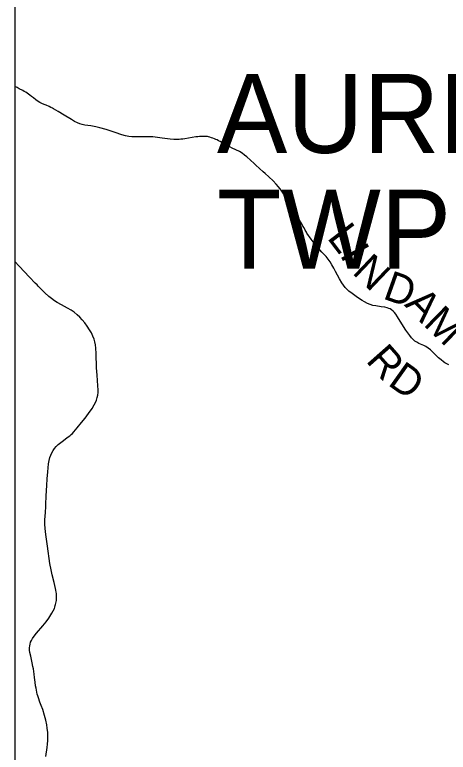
# Model space of a CAD drawing. Extents: x -10.5 to 40.6, y -3.2 to 22.
# Drawn here: x -10.544 to -9.719, y 16.355 to 17.758 of the extents above; entities that cross this region are included whole.
import ezdxf

# ---------------------------------------------------------------- set-up
doc = ezdxf.new("R2010")
doc.units = 0
for name, color, linetype in [('GM_X_Township_Road', 7, 'Continuous'), ('GM_X_Township_Road_Text', 7, 'Continuous'), ('GM_X_Township_Text', 7, 'Continuous')]:
    doc.layers.add(name, color=color, linetype=linetype)

msp = doc.modelspace()

# ---------------------------------------------------------------- linework, layer by layer
at = {"layer": 'GM_X_Township_Road'}
for points in [[(-9.7184, 17.092), (-9.7206, 17.093), (-9.7234, 17.0946), (-9.7257, 17.0959), (-9.7281, 17.0976), (-9.733, 17.1013), (-9.7376, 17.1054), (-9.7478, 17.1154), (-9.7533, 17.1205), (-9.7577, 17.124), (-9.7618, 17.1267), (-9.7657, 17.1287), (-9.7754, 17.1328), (-9.7793, 17.1348), (-9.7829, 17.1371), (-9.7863, 17.1399), (-9.7893, 17.1431), (-9.7927, 17.1475), (-9.8001, 17.1582), (-9.8076, 17.1697), (-9.816, 17.1835), (-9.8191, 17.1882), (-9.8218, 17.1916), (-9.8244, 17.1942), (-9.8273, 17.1965), (-9.8299, 17.1982), (-9.8327, 17.1994), (-9.8357, 17.2004), (-9.8399, 17.2014), (-9.8473, 17.2025), (-9.8571, 17.2039), (-9.8626, 17.2051), (-9.8679, 17.2067), (-9.8731, 17.2088), (-9.8786, 17.2116), (-9.8833, 17.2144), (-9.8923, 17.2202), (-9.9023, 17.2275), (-9.9083, 17.2322), (-9.9122, 17.2358), (-9.9154, 17.2392), (-9.9187, 17.2433), (-9.922, 17.2481), (-9.9264, 17.2556), (-9.934, 17.2695), (-9.9373, 17.2757), (-9.9407, 17.2821), (-9.9442, 17.2879), (-9.9478, 17.2929), (-9.9517, 17.2977), (-9.9555, 17.3018), (-9.9597, 17.3063), (-9.9635, 17.3104), (-9.9666, 17.314), (-9.97, 17.318), (-9.9733, 17.322), (-9.9766, 17.3261), (-9.9784, 17.3284), (-9.9805, 17.3312), (-9.9834, 17.3351), (-9.9855, 17.3381), (-9.9883, 17.3423), (-9.9893, 17.3441), (-9.9917, 17.3483), (-9.9938, 17.3523), (-9.9958, 17.3558), (-9.9981, 17.3599), (-10.0005, 17.3641), (-10.0033, 17.3688), (-10.0065, 17.3741), (-10.009, 17.3784), (-10.0116, 17.3826), (-10.0142, 17.3868), (-10.0175, 17.3921), (-10.0226, 17.4005), (-10.0325, 17.4164), (-10.0375, 17.424), (-10.0423, 17.4303), (-10.0466, 17.4354), (-10.0524, 17.4416), (-10.0608, 17.4495), (-10.0675, 17.4556), (-10.0715, 17.4591), (-10.0853, 17.4715), (-10.0889, 17.4748), (-10.1026, 17.4874), (-10.1069, 17.4909), (-10.1115, 17.4942), (-10.1168, 17.4974), (-10.1234, 17.5009), (-10.1305, 17.5042), (-10.1353, 17.5064), (-10.1391, 17.5083), (-10.1429, 17.5101), (-10.1463, 17.512), (-10.1537, 17.5165), (-10.1565, 17.5182), (-10.1591, 17.5196), (-10.1614, 17.5207), (-10.1642, 17.5219), (-10.1672, 17.523), (-10.1701, 17.5239), (-10.1729, 17.5247), (-10.1755, 17.5253), (-10.1778, 17.5259), (-10.1807, 17.5263), (-10.1835, 17.5264), (-10.1866, 17.5264), (-10.1895, 17.5264), (-10.1928, 17.5261), (-10.1961, 17.5258), (-10.1996, 17.5253), (-10.2204, 17.5219), (-10.2245, 17.5213), (-10.2285, 17.521), (-10.2318, 17.5207), (-10.2353, 17.5206), (-10.2415, 17.5206), (-10.2489, 17.5212), (-10.2637, 17.523), (-10.2816, 17.5252), (-10.289, 17.5257), (-10.2959, 17.5258), (-10.3064, 17.5255), (-10.3151, 17.5253), (-10.3213, 17.5257), (-10.3275, 17.5264), (-10.3336, 17.5277), (-10.3408, 17.5296), (-10.3532, 17.5335), (-10.3703, 17.5392), (-10.3823, 17.5426), (-10.3901, 17.5444), (-10.3999, 17.5463), (-10.4109, 17.5479), (-10.4164, 17.549), (-10.4206, 17.5502), (-10.4252, 17.552), (-10.4307, 17.5548), (-10.4366, 17.5584), (-10.4503, 17.5669), (-10.462, 17.5739), (-10.4706, 17.5789), (-10.4728, 17.58), (-10.4755, 17.5815), (-10.4789, 17.5831), (-10.4847, 17.5854), (-10.4887, 17.587), (-10.4932, 17.5891), (-10.497, 17.591), (-10.5002, 17.5929), (-10.5042, 17.5957), (-10.5085, 17.5994), (-10.5124, 17.6024), (-10.5158, 17.605), (-10.5184, 17.6068), (-10.5235, 17.6101), (-10.5264, 17.6118), (-10.5293, 17.6133), (-10.536, 17.6168), (-10.5401, 17.619), (-10.5443, 17.6213), (-10.5445, 17.6214)], [(-10.4855, 16.8225), (-10.4853, 16.8266), (-10.4844, 16.8432), (-10.4834, 16.8629), (-10.4827, 16.8753), (-10.4816, 16.8889), (-10.48, 16.9036), (-10.4789, 16.9104), (-10.4776, 16.9158), (-10.476, 16.9205), (-10.474, 16.925), (-10.4716, 16.9293), (-10.4688, 16.9332), (-10.4659, 16.9365), (-10.462, 16.9403), (-10.4545, 16.9464), (-10.4452, 16.9532), (-10.4425, 16.9551), (-10.4397, 16.9572), (-10.4372, 16.9593), (-10.4344, 16.9617), (-10.4318, 16.9646), (-10.4287, 16.9685), (-10.4255, 16.9724), (-10.4173, 16.9822), (-10.4107, 16.9905), (-10.404, 16.9995), (-10.3974, 17.0092), (-10.3933, 17.0161), (-10.3909, 17.0205), (-10.389, 17.025), (-10.3875, 17.0297), (-10.3865, 17.0346), (-10.3859, 17.0395), (-10.3858, 17.0444), (-10.3862, 17.0519), (-10.3878, 17.0723), (-10.3886, 17.0866), (-10.3893, 17.1133), (-10.39, 17.1238), (-10.3908, 17.13), (-10.392, 17.1355), (-10.3935, 17.1408), (-10.3957, 17.1466), (-10.3986, 17.1528), (-10.4019, 17.1588), (-10.4063, 17.1656), (-10.4111, 17.1721), (-10.4159, 17.1778), (-10.4206, 17.1827), (-10.4257, 17.1873), (-10.4316, 17.1919), (-10.4373, 17.1957), (-10.4442, 17.1998), (-10.4557, 17.206), (-10.4637, 17.2106), (-10.4689, 17.2139), (-10.4745, 17.2179), (-10.4798, 17.2222), (-10.4871, 17.2289), (-10.4959, 17.2376), (-10.4998, 17.2416), (-10.502, 17.2438), (-10.5055, 17.2473), (-10.5162, 17.2586), (-10.5362, 17.2799), (-10.5445, 17.2884)], [(-10.4856, 16.3473), (-10.4828, 16.3645), (-10.4821, 16.3707), (-10.4817, 16.3781), (-10.4815, 16.3856), (-10.4818, 16.393), (-10.4825, 16.4011), (-10.4836, 16.4078), (-10.4853, 16.4164), (-10.4877, 16.4254), (-10.4913, 16.4366), (-10.4941, 16.4446), (-10.4964, 16.4506), (-10.4993, 16.4588), (-10.5006, 16.4627), (-10.5015, 16.4661), (-10.5024, 16.4698), (-10.5031, 16.4732), (-10.5039, 16.4776), (-10.5047, 16.4818), (-10.5055, 16.4886), (-10.5068, 16.4978), (-10.5075, 16.5038), (-10.5082, 16.5088), (-10.5089, 16.5138), (-10.5098, 16.5185), (-10.511, 16.5253), (-10.5125, 16.532), (-10.5139, 16.538), (-10.5155, 16.5452), (-10.5161, 16.5495), (-10.5162, 16.5539), (-10.5159, 16.5576), (-10.5152, 16.5612), (-10.5142, 16.5647), (-10.5127, 16.5681), (-10.5106, 16.5719), (-10.5077, 16.5759), (-10.5029, 16.5816), (-10.4907, 16.5956), (-10.4846, 16.6033), (-10.4797, 16.6104), (-10.4737, 16.6196), (-10.4711, 16.6245), (-10.4691, 16.629), (-10.4681, 16.6316), (-10.4673, 16.6342), (-10.4667, 16.6363), (-10.4661, 16.639), (-10.4656, 16.6413), (-10.4653, 16.6439), (-10.4651, 16.6463), (-10.4649, 16.6488), (-10.4649, 16.6514), (-10.465, 16.6537), (-10.4652, 16.6572), (-10.4655, 16.6598), (-10.4661, 16.6636), (-10.4666, 16.6665), (-10.4693, 16.6779), (-10.4732, 16.6929), (-10.4752, 16.702), (-10.4775, 16.7142), (-10.4823, 16.7473), (-10.4855, 16.7693), (-10.4866, 16.781), (-10.487, 16.789), (-10.4869, 16.7976), (-10.4862, 16.8112), (-10.4855, 16.8225)]]:
    msp.add_lwpolyline(points, dxfattribs=at)
at = {"layer": 'GM_X_Township_Text'}
msp.add_lwpolyline([(-10.5445, 19.4241), (-10.5445, 16.0741), (-10.3151, 16.0685), (-10.1031, 16.0664), (-9.5534, 16.0497), (-8.7017, 16.0275), (-8.5879, 16.0247), (-8.2615, 16.0223), (-8.2451, 17.3912), (-8.2441, 17.4134)], dxfattribs=at)

# ---------------------------------------------------------------- texts
at = {"layer": 'GM_X_Township_Road_Text'}
for s, rotation, p in [('L', 307.3593, (-9.9512, 17.3335)), ('I', 299.3169, (-9.9266, 17.3015)), ('N', 316.4091, (-9.9039, 17.2666)), ('D', 340.4044, (-9.8457, 17.2186)), ('A', 314.1474, (-9.8043, 17.2055)), ('M', 315.7458, (-9.7683, 17.1684)), ('R', 311.4485, (-9.8776, 17.0992)), ('D', 324.5887, (-9.8363, 17.0549))]:
    msp.add_text(s, height=0.0568, rotation=rotation, dxfattribs=at).set_placement(p)
at = {"layer": 'GM_X_Township_Text'}
for s, p in [('AURELIUS', (-10.1595, 17.4949)), ('TWP', (-10.1595, 17.2749))]:
    msp.add_text(s, height=0.15, rotation=0, dxfattribs=at).set_placement(p)

doc.saveas('drawing.dxf')
